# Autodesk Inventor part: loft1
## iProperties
Shininess: 64.0
Length Units: 11269
Angle Units: 11279
Time Units: 11290
Mass Units: 11283
Length Display Precision: 3
Angle Display Precision: 2
Compacted: True
Part Number: loft1
Document SubType Name: Modeling
Created: 2002-12
Designer: deepak
Density: 0.0
Volumn: 0.0
Area: 0.0
PropertySet Name: Model Information
Control State: 0
Master: False
Checked Out: False
Author: deepak
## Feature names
1. Loft3
